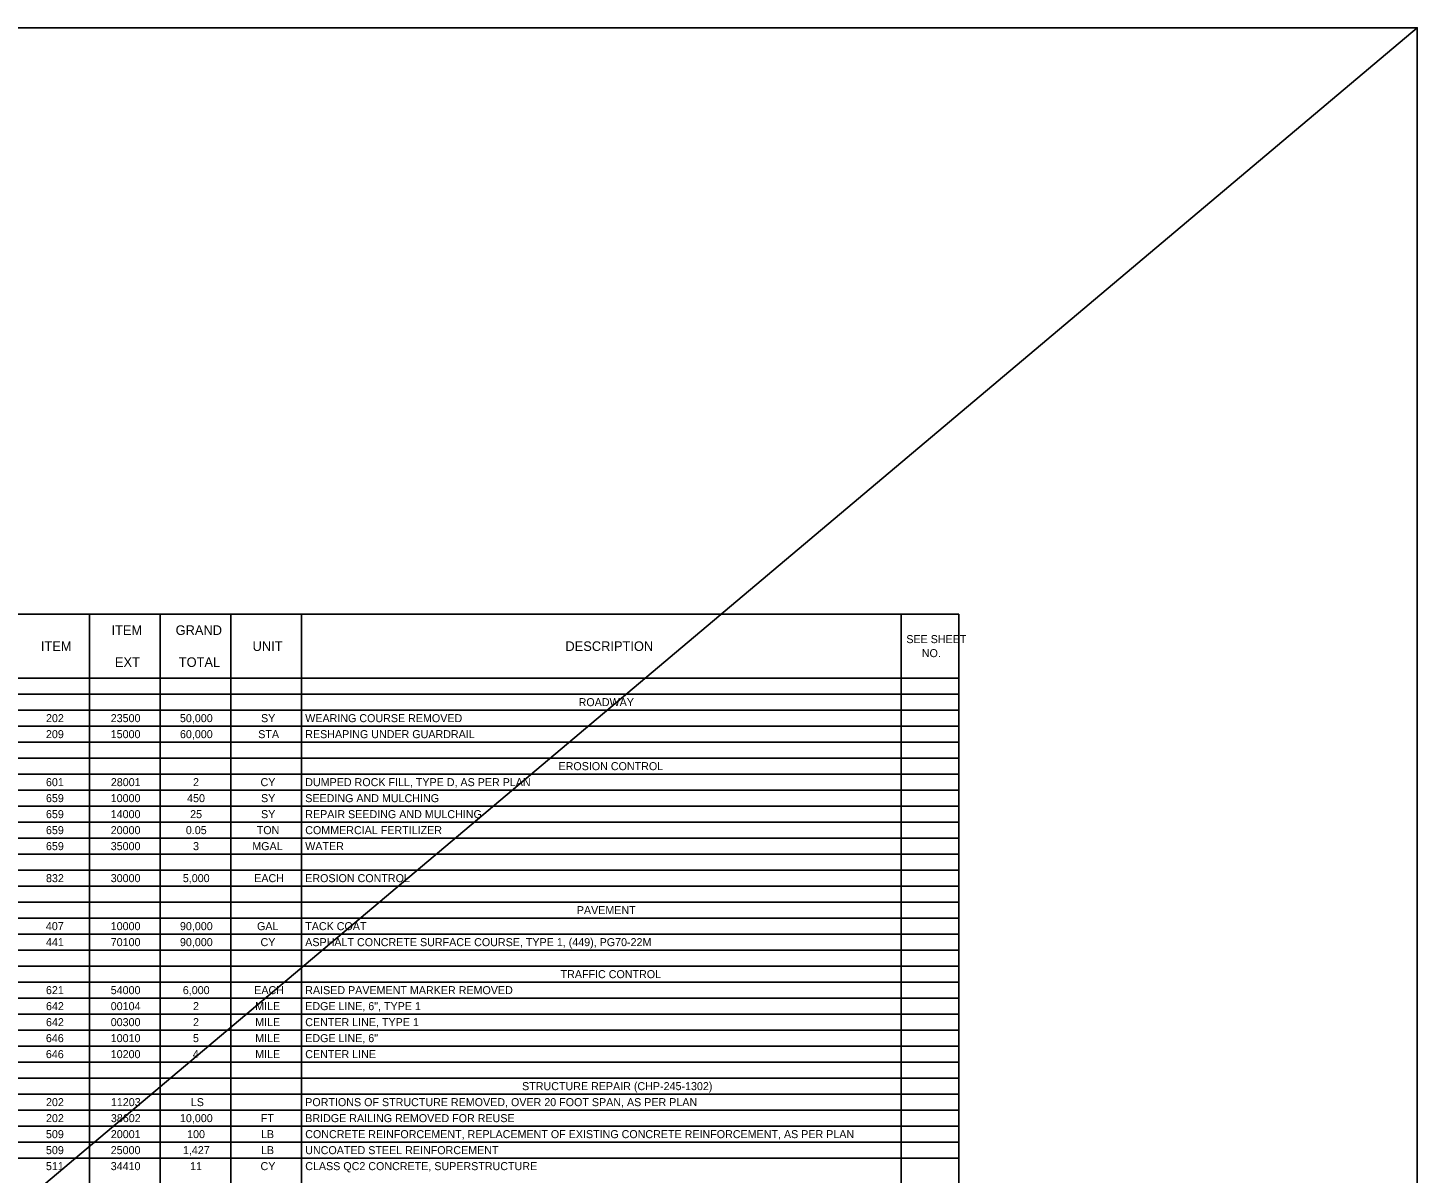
# Model space of a CAD drawing. Extents: x -58.2 to 35.9, y -5.7 to 34.4.
# Drawn here: x -34.85 to -10.54, y 14.4 to 34.45 of the extents above; entities that cross this region are included whole.
import ezdxf

# ---------------------------------------------------------------- set-up
doc = ezdxf.new("R2010")
doc.units = 0
for name, color, linetype in [('SC_Scratch1', 7, 'Continuous'), ('SH_Data', 7, 'Continuous'), ('SH_Text', 7, 'Continuous')]:
    doc.layers.add(name, color=color, linetype=linetype)

msp = doc.modelspace()

# ---------------------------------------------------------------- linework, layer by layer
at = {"layer": 'SC_Scratch1'}
msp.add_line((-58.206, -5.726), (-10.544, 34.449), dxfattribs=at)
msp.add_lwpolyline([(-58.206, 34.449), (-10.544, 34.449), (-10.544, -5.726), (-58.206, -5.726)], close=True, dxfattribs=at)
at = {"layer": 'SH_Data'}
for p, q in [((-49.066, 24.187), (-18.563, 24.187)), ((-33.765, 24.187), (-33.765, 3.187)), ((-32.53, 24.187), (-32.53, 3.187)), ((-31.294, 24.187), (-31.294, 3.187)), ((-30.059, 24.187), (-30.059, 3.187)), ((-19.567, 24.187), (-19.567, 3.187)), ((-18.563, 24.187), (-18.563, 3.187)), ((-49.066, 23.067), (-18.563, 23.067)), ((-49.066, 22.787), (-18.563, 22.787)), ((-49.066, 22.507), (-18.563, 22.507)), ((-49.066, 22.227), (-18.563, 22.227)), ((-49.066, 21.947), (-18.563, 21.947)), ((-49.066, 21.667), (-18.563, 21.667)), ((-49.066, 21.387), (-18.563, 21.387)), ((-49.066, 21.107), (-18.563, 21.107)), ((-49.066, 20.827), (-18.563, 20.827)), ((-49.066, 20.547), (-18.563, 20.547)), ((-49.066, 20.267), (-18.563, 20.267)), ((-49.066, 19.987), (-18.563, 19.987)), ((-49.066, 19.707), (-18.563, 19.707)), ((-49.066, 19.427), (-18.563, 19.427)), ((-49.066, 19.147), (-18.563, 19.147)), ((-49.066, 18.867), (-18.563, 18.867)), ((-49.066, 18.587), (-18.563, 18.587)), ((-49.066, 18.307), (-18.563, 18.307)), ((-49.066, 18.027), (-18.563, 18.027)), ((-49.066, 17.747), (-18.563, 17.747)), ((-49.066, 17.467), (-18.563, 17.467)), ((-49.066, 17.187), (-18.563, 17.187)), ((-49.066, 16.907), (-18.563, 16.907)), ((-49.066, 16.627), (-18.563, 16.627)), ((-49.066, 16.347), (-18.563, 16.347)), ((-49.066, 16.067), (-18.563, 16.067)), ((-49.066, 15.787), (-18.563, 15.787)), ((-49.066, 15.507), (-18.563, 15.507)), ((-49.066, 15.227), (-18.563, 15.227)), ((-49.066, 14.947), (-18.563, 14.947)), ((-49.066, 14.667), (-18.563, 14.667))]:
    msp.add_line(p, q, dxfattribs=at)

# ---------------------------------------------------------------- texts
at = {"layer": 'SH_Text'}
for s, height, p in [('ITEM', 0.168, (-33.382, 23.823)), ('GRAND', 0.168, (-32.26, 23.823)), ('SEE SHEET ', 0.14, (-19.48, 23.68)), ('ITEM', 0.168, (-34.617, 23.543)), ('UNIT', 0.168, (-30.914, 23.543)), ('DESCRIPTION', 0.168, (-25.442, 23.543)), ('NO.', 0.14, (-19.209, 23.435)), ('EXT', 0.168, (-33.322, 23.263)), ('TOTAL', 0.168, (-32.205, 23.263)), ('ROADWAY', 0.14, (-25.211, 22.577)), ('202', 0.14, (-34.527, 22.297)), ('23500', 0.14, (-33.395, 22.297)), ('50,000', 0.14, (-32.184, 22.297)), ('SY', 0.14, (-30.766, 22.297)), ('WEARING COURSE REMOVED', 0.14, (-29.993, 22.297)), ('209', 0.14, (-34.528, 22.017)), ('15000', 0.14, (-33.395, 22.017)), ('60,000', 0.14, (-32.184, 22.017)), ('STA', 0.14, (-30.815, 22.017)), ('RESHAPING UNDER GUARDRAIL', 0.14, (-29.993, 22.017)), ('EROSION CONTROL', 0.14, (-25.563, 21.457)), ('601', 0.14, (-34.528, 21.177)), ('28001', 0.14, (-33.393, 21.177)), ('2', 0.14, (-31.956, 21.177)), ('CY', 0.14, (-30.775, 21.177)), ('DUMPED ROCK FILL, TYPE D, AS PER PLAN', 0.14, (-29.993, 21.177)), ('659', 0.14, (-34.528, 20.897)), ('10000', 0.14, (-33.395, 20.897)), ('450', 0.14, (-32.059, 20.897)), ('SY', 0.14, (-30.766, 20.897)), ('SEEDING AND MULCHING', 0.14, (-29.993, 20.897)), ('659', 0.14, (-34.528, 20.617)), ('14000', 0.14, (-33.395, 20.617)), ('25', 0.14, (-32.006, 20.617)), ('SY', 0.14, (-30.766, 20.617)), ('REPAIR SEEDING AND MULCHING', 0.14, (-29.993, 20.617)), ('659', 0.14, (-34.528, 20.337)), ('20000', 0.14, (-33.395, 20.337)), ('0.05', 0.14, (-32.081, 20.337)), ('TON', 0.14, (-30.841, 20.337)), ('COMMERCIAL FERTILIZER', 0.14, (-29.993, 20.337)), ('659', 0.14, (-34.528, 20.057)), ('35000', 0.14, (-33.395, 20.057)), ('3', 0.14, (-31.955, 20.057)), ('MGAL', 0.14, (-30.919, 20.057)), ('WATER', 0.14, (-29.993, 20.057)), ('832', 0.14, (-34.527, 19.497)), ('30000', 0.14, (-33.395, 19.497)), ('5,000', 0.14, (-32.134, 19.497)), ('EACH', 0.14, (-30.885, 19.497)), ('EROSION CONTROL', 0.14, (-29.993, 19.497)), ('PAVEMENT', 0.14, (-25.243, 18.937)), ('407', 0.14, (-34.529, 18.657)), ('10000', 0.14, (-33.395, 18.657)), ('90,000', 0.14, (-32.184, 18.657)), ('GAL', 0.14, (-30.836, 18.657)), ('TACK COAT', 0.14, (-29.993, 18.657)), ('441', 0.14, (-34.528, 18.377)), ('70100', 0.14, (-33.395, 18.377)), ('90,000', 0.14, (-32.184, 18.377)), ('CY', 0.14, (-30.775, 18.377)), ('ASPHALT CONCRETE SURFACE COURSE, TYPE 1, (449), PG70-22M', 0.14, (-29.993, 18.377)), ('TRAFFIC CONTROL', 0.14, (-25.527, 17.817)), ('621', 0.14, (-34.528, 17.537)), ('54000', 0.14, (-33.395, 17.537)), ('6,000', 0.14, (-32.134, 17.537)), ('EACH', 0.14, (-30.885, 17.537)), ('RAISED PAVEMENT MARKER REMOVED', 0.14, (-29.993, 17.537)), ('642', 0.14, (-34.527, 17.257)), ('00104', 0.14, (-33.395, 17.257)), ('2', 0.14, (-31.956, 17.257)), ('MILE', 0.14, (-30.869, 17.257)), ('EDGE LINE, 6", TYPE 1', 0.14, (-29.993, 17.257)), ('642', 0.14, (-34.527, 16.977)), ('00300', 0.14, (-33.395, 16.977)), ('2', 0.14, (-31.956, 16.977)), ('MILE', 0.14, (-30.869, 16.977)), ('CENTER LINE, TYPE 1', 0.14, (-29.993, 16.977)), ('646', 0.14, (-34.529, 16.697)), ('10010', 0.14, (-33.395, 16.697)), ('5', 0.14, (-31.956, 16.697)), ('MILE', 0.14, (-30.869, 16.697)), ('EDGE LINE, 6"', 0.14, (-29.993, 16.697)), ('646', 0.14, (-34.529, 16.417)), ('10200', 0.14, (-33.395, 16.417)), ('4', 0.14, (-31.959, 16.417)), ('MILE', 0.14, (-30.869, 16.417)), ('CENTER LINE', 0.14, (-29.993, 16.417)), ('STRUCTURE REPAIR (CHP-245-1302)', 0.14, (-26.2, 15.857)), ('202', 0.14, (-34.527, 15.577)), ('11203', 0.14, (-33.392, 15.577)), ('LS', 0.14, (-31.994, 15.577)), ('PORTIONS OF STRUCTURE REMOVED, OVER 20 FOOT SPAN, AS PER PLAN', 0.14, (-29.993, 15.577)), ('202', 0.14, (-34.527, 15.297)), ('38602', 0.14, (-33.392, 15.297)), ('10,000', 0.14, (-32.184, 15.297)), ('FT', 0.14, (-30.77, 15.297)), ('BRIDGE RAILING REMOVED FOR REUSE', 0.14, (-29.993, 15.297)), ('509', 0.14, (-34.528, 15.017)), ('20001', 0.14, (-33.393, 15.017)), ('100', 0.14, (-32.059, 15.017)), ('LB', 0.14, (-30.767, 15.017)), ('CONCRETE REINFORCEMENT, REPLACEMENT OF EXISTING CONCRETE REINFORCEMENT, AS PER PLAN', 0.14, (-29.993, 15.017)), ('509', 0.14, (-34.528, 14.737)), ('25000', 0.14, (-33.395, 14.737)), ('1,427', 0.14, (-32.132, 14.737)), ('LB', 0.14, (-30.767, 14.737)), ('UNCOATED STEEL REINFORCEMENT', 0.14, (-29.993, 14.737)), ('511', 0.14, (-34.528, 14.457)), ('34410', 0.14, (-33.395, 14.457)), ('11', 0.14, (-32.007, 14.457)), ('CY', 0.14, (-30.775, 14.457)), ('CLASS QC2 CONCRETE, SUPERSTRUCTURE', 0.14, (-29.993, 14.457))]:
    msp.add_text(s, height=height, dxfattribs=at).set_placement(p)

doc.saveas('drawing.dxf')
